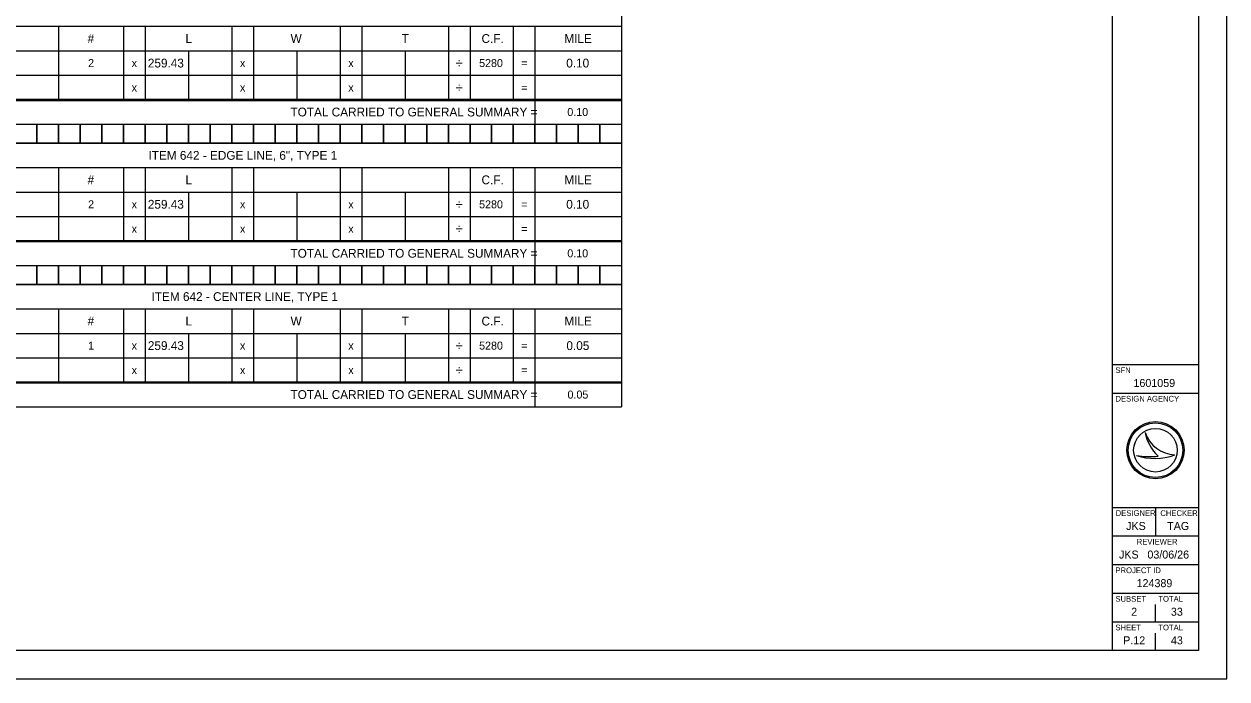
# Model space of a CAD drawing. Extents: x 0 to 34, y 0 to 22.
# Drawn here: x 12.96 to 34, y 0 to 11.45 of the extents above; entities that cross this region are included whole.
import ezdxf

# ---------------------------------------------------------------- set-up
doc = ezdxf.new("R2010")
doc.units = 0
for name, color, linetype in [('Default', 7, 'Continuous'), ('SH_Border', 7, 'Continuous'), ('SH_Cut_Line', 7, 'Continuous'), ('SH_Data', 7, 'Continuous')]:
    doc.layers.add(name, color=color, linetype=linetype)

msp = doc.modelspace()

# ---------------------------------------------------------------- linework, layer by layer
at = {"layer": 'Default'}
for p, q in [((23.412, 12.61), (23.412, 10.117)), ((10.153, 11.413), (23.412, 11.413)), ((13.563, 11.413), (13.563, 10.139)), ((14.699, 11.413), (14.699, 10.139)), ((15.078, 11.413), (15.078, 10.139)), ((16.593, 11.413), (16.593, 10.139)), ((16.972, 11.413), (16.972, 10.139)), ((18.488, 11.413), (18.488, 10.139)), ((18.866, 11.413), (18.866, 10.139)), ((20.382, 11.413), (20.382, 10.139)), ((20.761, 11.413), (20.761, 10.139)), ((21.518, 11.413), (21.518, 10.139)), ((21.897, 11.413), (21.897, 10.139)), ((10.153, 10.985), (23.412, 10.985)), ((15.836, 10.985), (15.836, 10.139)), ((17.73, 10.985), (17.73, 10.139)), ((19.624, 10.985), (19.624, 10.139)), ((10.153, 10.556), (23.412, 10.556)), ((10.153, 10.139), (23.412, 10.139)), ((10.153, 10.117), (23.412, 10.117)), ((21.897, 10.117), (21.897, 9.7)), ((23.412, 10.139), (23.412, 7.647)), ((10.153, 9.7), (23.412, 9.7)), ((10.153, 9.37), (23.412, 9.37)), ((10.153, 8.942), (23.412, 8.942)), ((13.563, 8.942), (13.563, 7.669)), ((14.699, 8.942), (14.699, 7.669)), ((15.078, 8.942), (15.078, 7.669)), ((16.593, 8.942), (16.593, 7.669)), ((16.972, 8.942), (16.972, 7.669)), ((18.488, 8.942), (18.488, 7.669)), ((18.866, 8.942), (18.866, 7.669)), ((20.382, 8.942), (20.382, 7.669)), ((20.761, 8.942), (20.761, 7.669)), ((21.518, 8.942), (21.518, 7.669)), ((21.897, 8.942), (21.897, 7.669)), ((10.153, 8.514), (23.412, 8.514)), ((15.836, 8.514), (15.836, 7.669)), ((17.73, 8.514), (17.73, 7.669)), ((19.624, 8.514), (19.624, 7.669)), ((10.153, 8.086), (23.412, 8.086)), ((10.153, 7.669), (23.412, 7.669)), ((10.153, 7.647), (23.412, 7.647)), ((21.897, 7.647), (21.897, 7.229)), ((23.412, 7.669), (23.412, 5.176)), ((10.153, 7.229), (23.412, 7.229)), ((10.153, 6.9), (23.412, 6.9)), ((10.153, 6.472), (23.412, 6.472)), ((13.563, 6.472), (13.563, 5.198)), ((14.699, 6.472), (14.699, 5.198)), ((15.078, 6.472), (15.078, 5.198)), ((16.593, 6.472), (16.593, 5.198)), ((16.972, 6.472), (16.972, 5.198)), ((18.488, 6.472), (18.488, 5.198)), ((18.866, 6.472), (18.866, 5.198)), ((20.382, 6.472), (20.382, 5.198)), ((20.761, 6.472), (20.761, 5.198)), ((21.518, 6.472), (21.518, 5.198)), ((21.897, 6.472), (21.897, 5.198)), ((10.153, 6.043), (23.412, 6.043)), ((15.836, 6.043), (15.836, 5.198)), ((17.73, 6.043), (17.73, 5.198)), ((19.624, 6.043), (19.624, 5.198)), ((10.153, 5.615), (23.412, 5.615)), ((10.153, 5.198), (23.412, 5.198)), ((10.153, 5.176), (23.412, 5.176)), ((21.897, 5.176), (21.897, 4.759)), ((23.412, 5.198), (23.412, 4.759)), ((10.153, 4.759), (23.412, 4.759))]:
    msp.add_line(p, q, dxfattribs=at)
for points in [[(12.805, 9.7), (13.184, 9.7), (13.184, 9.37), (12.805, 9.37)], [(13.184, 9.7), (13.563, 9.7), (13.563, 9.37), (13.184, 9.37)], [(13.563, 9.7), (13.942, 9.7), (13.942, 9.37), (13.563, 9.37)], [(13.942, 9.7), (14.321, 9.7), (14.321, 9.37), (13.942, 9.37)], [(14.321, 9.7), (14.699, 9.7), (14.699, 9.37), (14.321, 9.37)], [(14.699, 9.7), (15.078, 9.7), (15.078, 9.37), (14.699, 9.37)], [(15.078, 9.7), (15.457, 9.7), (15.457, 9.37), (15.078, 9.37)], [(15.457, 9.7), (15.836, 9.7), (15.836, 9.37), (15.457, 9.37)], [(15.836, 9.7), (16.215, 9.7), (16.215, 9.37), (15.836, 9.37)], [(16.215, 9.7), (16.593, 9.7), (16.593, 9.37), (16.215, 9.37)], [(16.593, 9.7), (16.972, 9.7), (16.972, 9.37), (16.593, 9.37)], [(16.972, 9.7), (17.351, 9.7), (17.351, 9.37), (16.972, 9.37)], [(17.351, 9.7), (17.73, 9.7), (17.73, 9.37), (17.351, 9.37)], [(17.73, 9.7), (18.109, 9.7), (18.109, 9.37), (17.73, 9.37)], [(18.109, 9.7), (18.488, 9.7), (18.488, 9.37), (18.109, 9.37)], [(18.488, 9.7), (18.866, 9.7), (18.866, 9.37), (18.488, 9.37)], [(18.866, 9.7), (19.245, 9.7), (19.245, 9.37), (18.866, 9.37)], [(19.245, 9.7), (19.624, 9.7), (19.624, 9.37), (19.245, 9.37)], [(19.624, 9.7), (20.003, 9.7), (20.003, 9.37), (19.624, 9.37)], [(20.003, 9.7), (20.382, 9.7), (20.382, 9.37), (20.003, 9.37)], [(20.382, 9.7), (20.761, 9.7), (20.761, 9.37), (20.382, 9.37)], [(20.761, 9.7), (21.139, 9.7), (21.139, 9.37), (20.761, 9.37)], [(21.139, 9.7), (21.518, 9.7), (21.518, 9.37), (21.139, 9.37)], [(21.518, 9.7), (21.897, 9.7), (21.897, 9.37), (21.518, 9.37)], [(21.897, 9.7), (22.276, 9.7), (22.276, 9.37), (21.897, 9.37)], [(22.276, 9.7), (22.655, 9.7), (22.655, 9.37), (22.276, 9.37)], [(22.655, 9.7), (23.034, 9.7), (23.034, 9.37), (22.655, 9.37)], [(23.034, 9.7), (23.412, 9.7), (23.412, 9.37), (23.034, 9.37)], [(12.805, 7.229), (13.184, 7.229), (13.184, 6.9), (12.805, 6.9)], [(13.184, 7.229), (13.563, 7.229), (13.563, 6.9), (13.184, 6.9)], [(13.563, 7.229), (13.942, 7.229), (13.942, 6.9), (13.563, 6.9)], [(13.942, 7.229), (14.321, 7.229), (14.321, 6.9), (13.942, 6.9)], [(14.321, 7.229), (14.699, 7.229), (14.699, 6.9), (14.321, 6.9)], [(14.699, 7.229), (15.078, 7.229), (15.078, 6.9), (14.699, 6.9)], [(15.078, 7.229), (15.457, 7.229), (15.457, 6.9), (15.078, 6.9)], [(15.457, 7.229), (15.836, 7.229), (15.836, 6.9), (15.457, 6.9)], [(15.836, 7.229), (16.215, 7.229), (16.215, 6.9), (15.836, 6.9)], [(16.215, 7.229), (16.593, 7.229), (16.593, 6.9), (16.215, 6.9)], [(16.593, 7.229), (16.972, 7.229), (16.972, 6.9), (16.593, 6.9)], [(16.972, 7.229), (17.351, 7.229), (17.351, 6.9), (16.972, 6.9)], [(17.351, 7.229), (17.73, 7.229), (17.73, 6.9), (17.351, 6.9)], [(17.73, 7.229), (18.109, 7.229), (18.109, 6.9), (17.73, 6.9)], [(18.109, 7.229), (18.488, 7.229), (18.488, 6.9), (18.109, 6.9)], [(18.488, 7.229), (18.866, 7.229), (18.866, 6.9), (18.488, 6.9)], [(18.866, 7.229), (19.245, 7.229), (19.245, 6.9), (18.866, 6.9)], [(19.245, 7.229), (19.624, 7.229), (19.624, 6.9), (19.245, 6.9)], [(19.624, 7.229), (20.003, 7.229), (20.003, 6.9), (19.624, 6.9)], [(20.003, 7.229), (20.382, 7.229), (20.382, 6.9), (20.003, 6.9)], [(20.382, 7.229), (20.761, 7.229), (20.761, 6.9), (20.382, 6.9)], [(20.761, 7.229), (21.139, 7.229), (21.139, 6.9), (20.761, 6.9)], [(21.139, 7.229), (21.518, 7.229), (21.518, 6.9), (21.139, 6.9)], [(21.518, 7.229), (21.897, 7.229), (21.897, 6.9), (21.518, 6.9)], [(21.897, 7.229), (22.276, 7.229), (22.276, 6.9), (21.897, 6.9)], [(22.276, 7.229), (22.655, 7.229), (22.655, 6.9), (22.276, 6.9)], [(22.655, 7.229), (23.034, 7.229), (23.034, 6.9), (22.655, 6.9)], [(23.034, 7.229), (23.412, 7.229), (23.412, 6.9), (23.034, 6.9)]]:
    msp.add_lwpolyline(points, close=True, dxfattribs=at)
at = {"layer": 'SH_Border'}
for p, q in [((32, 0.5), (32, 21.5)), ((32, 5.5), (33.5, 5.5)), ((32, 5), (33.5, 5)), ((32, 3), (33.5, 3)), ((32.75, 3), (32.75, 2.5)), ((32, 2.5), (33.5, 2.5)), ((32, 2), (33.5, 2)), ((32, 1.5), (33.5, 1.5)), ((32, 1), (33.5, 1))]:
    msp.add_line(p, q, dxfattribs=at)
msp.add_lwpolyline([(1.5, 21.5), (33.5, 21.5), (33.5, 0.5), (1.5, 0.5)], close=True, dxfattribs=at)
at = {"layer": 'SH_Cut_Line'}
msp.add_lwpolyline([(0, 0), (34, 0), (34, 22), (0, 22)], close=True, dxfattribs=at)
at = {"layer": 'SH_Data'}
for p, q in [((32.567, 4.31), (32.567, 4.31)), ((32.75, 4), (32.75, 4)), ((32.417, 3.91), (32.417, 3.91)), ((33.087, 3.919), (33.087, 3.919)), ((32.75, 1), (32.75, 1.3)), ((32.375, 0.675), (32.375, 0.675)), ((32.75, 0.5), (32.75, 0.8))]:
    msp.add_line(p, q, dxfattribs=at)
for radius in [0.5, 0.477, 0.477, 0.382]:
    msp.add_circle((32.75, 4), radius, dxfattribs=at)
for centre, radius, start, end in [((33.116, 4.498), 0.58, 198.9257, 198.9319), ((33.347, 4.47), 0.796, 191.6379, 191.6421), ((33.116, 4.498), 0.58, 198.9319, 267.1657), ((33.347, 4.47), 0.796, 191.6421, 226.0947), ((32.739, 4.87), 1.013, 251.4576, 290.0832), ((32.648, 5.154), 1.266, 259.4964, 259.4995), ((32.739, 4.87), 1.013, 251.4527, 251.4576), ((32.648, 5.154), 1.266, 259.4995, 276.6672)]:
    msp.add_arc(centre, radius, start, end, dxfattribs=at)

# ---------------------------------------------------------------- texts
at = {"layer": 'Default'}
for s, height, p in [('#', 0.154, (14.072, 11.122)), ('L', 0.154, (15.785, 11.122)), ('W', 0.154, (17.623, 11.122)), ('T', 0.154, (19.565, 11.122)), ('C.F.', 0.154, (20.962, 11.122)), ('MILE', 0.154, (22.411, 11.122)), ('2', 0.14, (14.081, 10.7)), ('x', 0.14, (14.843, 10.7)), ('259.43', 0.154, (15.126, 10.693)), ('x', 0.14, (16.737, 10.7)), ('x', 0.14, (18.632, 10.7)), ('÷', 0.168, (20.509, 10.686)), ('5280', 0.14, (20.92, 10.7)), ('=', 0.14, (21.658, 10.7)), ('0.10', 0.154, (22.444, 10.693)), ('x', 0.14, (14.843, 10.272)), ('x', 0.14, (16.737, 10.272)), ('x', 0.14, (18.632, 10.272)), ('÷', 0.168, (20.509, 10.258)), ('=', 0.14, (21.658, 10.272)), ('TOTAL CARRIED TO GENERAL SUMMARY =', 0.154, (17.621, 9.837)), ('0.10', 0.14, (22.463, 9.844)), ('ITEM 642 - EDGE LINE, 6", TYPE 1', 0.154, (15.137, 9.079)), ('#', 0.154, (14.072, 8.651)), ('L', 0.154, (15.785, 8.651)), ('C.F.', 0.154, (20.962, 8.651)), ('MILE', 0.154, (22.411, 8.651)), ('2', 0.14, (14.081, 8.23)), ('x', 0.14, (14.843, 8.23)), ('259.43', 0.154, (15.126, 8.223)), ('x', 0.14, (16.737, 8.23)), ('x', 0.14, (18.632, 8.23)), ('÷', 0.168, (20.509, 8.216)), ('5280', 0.14, (20.92, 8.23)), ('=', 0.14, (21.658, 8.23)), ('0.10', 0.154, (22.444, 8.223)), ('x', 0.14, (14.843, 7.802)), ('x', 0.14, (16.737, 7.802)), ('x', 0.14, (18.632, 7.802)), ('÷', 0.168, (20.509, 7.788)), ('=', 0.14, (21.658, 7.802)), ('TOTAL CARRIED TO GENERAL SUMMARY =', 0.154, (17.621, 7.366)), ('0.10', 0.14, (22.463, 7.373)), ('ITEM 642 - CENTER LINE, TYPE 1', 0.154, (15.191, 6.609)), ('#', 0.154, (14.072, 6.181)), ('L', 0.154, (15.785, 6.181)), ('W', 0.154, (17.623, 6.181)), ('T', 0.154, (19.565, 6.181)), ('C.F.', 0.154, (20.962, 6.181)), ('MILE', 0.154, (22.411, 6.181)), ('1', 0.14, (14.081, 5.759)), ('259.43', 0.154, (15.126, 5.752)), ('5280', 0.14, (20.92, 5.759)), ('0.05', 0.154, (22.447, 5.752)), ('x', 0.14, (14.843, 5.759)), ('x', 0.14, (16.737, 5.759)), ('x', 0.14, (18.632, 5.759)), ('÷', 0.168, (20.509, 5.745)), ('=', 0.14, (21.658, 5.759)), ('x', 0.14, (14.843, 5.331)), ('x', 0.14, (16.737, 5.331)), ('x', 0.14, (18.632, 5.331)), ('÷', 0.168, (20.509, 5.317)), ('=', 0.14, (21.658, 5.331)), ('TOTAL CARRIED TO GENERAL SUMMARY =', 0.154, (17.621, 4.896)), ('0.05', 0.14, (22.466, 4.903))]:
    msp.add_text(s, height=height, dxfattribs=at).set_placement(p)
at = {"layer": 'SH_Data'}
for s, height, p in [('SFN', 0.1, (32.05, 5.35)), ('1601059', 0.14, (32.365, 5.105)), ('DESIGN AGENCY', 0.1, (32.05, 4.85)), ('DESIGNER', 0.1, (32.054, 2.85)), ('CHECKER', 0.1, (32.835, 2.85)), ('JKS', 0.14, (32.237, 2.605)), ('TAG', 0.14, (32.955, 2.605)), ('REVIEWER', 0.1, (32.422, 2.35)), ('JKS', 0.14, (32.112, 2.105)), ('03/06/26', 0.14, (32.609, 2.105)), ('PROJECT ID', 0.1, (32.05, 1.85)), ('124389', 0.14, (32.42, 1.605)), ('SUBSET', 0.1, (32.05, 1.35)), ('TOTAL', 0.1, (32.8, 1.35)), ('2', 0.14, (32.325, 1.105)), ('33', 0.14, (33.02, 1.105)), ('SHEET', 0.1, (32.05, 0.85)), ('TOTAL', 0.1, (32.8, 0.85)), ('P.12', 0.14, (32.185, 0.605)), ('43', 0.14, (33.02, 0.605))]:
    msp.add_text(s, height=height, dxfattribs=at).set_placement(p)

doc.saveas('drawing.dxf')
